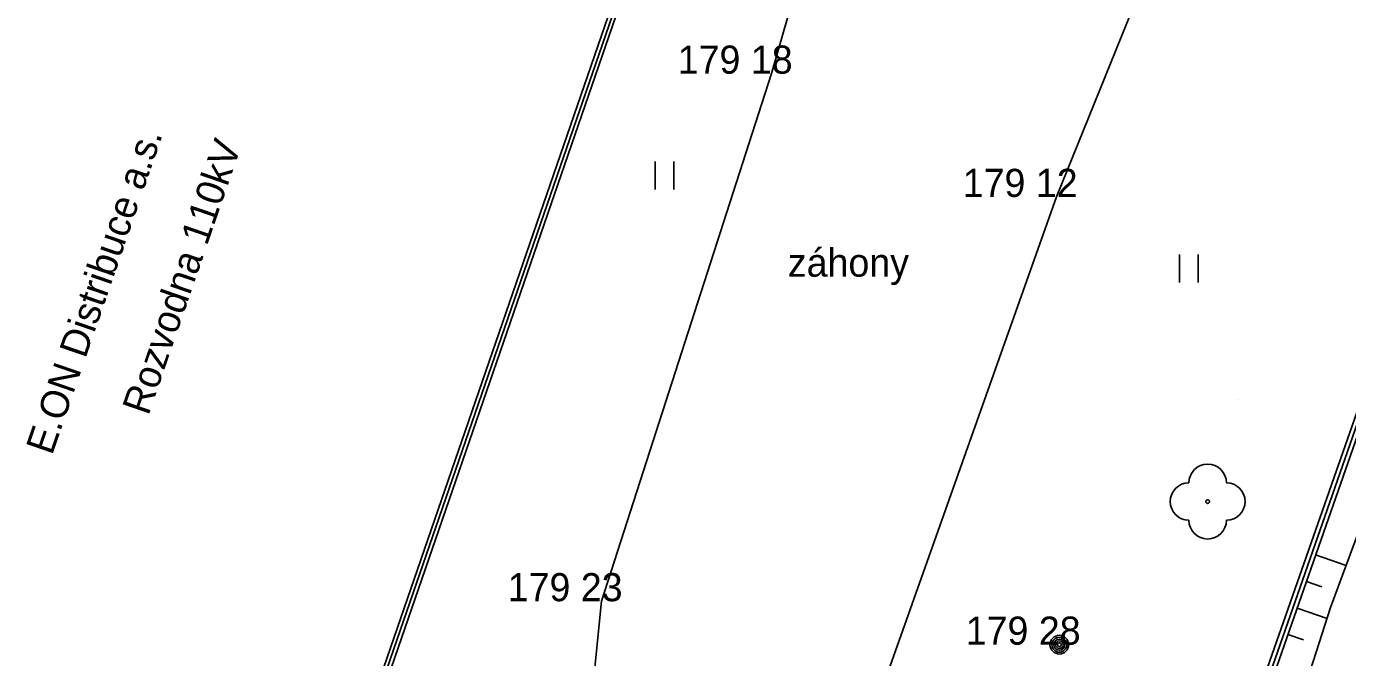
# Model space of a CAD drawing. Extents: x -537755 to -537431, y -1180722 to -1180510.
# Drawn here: x -537503.04 to -537467.76, y -1180590.89 to -1180574.05 of the extents above; entities that cross this region are included whole.
import ezdxf

# ---------------------------------------------------------------- set-up
doc = ezdxf.new("R2010")
doc.units = 0
for name, color, linetype in [('Vrstva 1', 7, 'Continuous'), ('Vrstva 14', 7, 'Continuous'), ('Vrstva 15', 7, 'Continuous'), ('Vrstva 22', 7, 'Continuous'), ('Vrstva 23', 7, 'Continuous'), ('Vrstva 25', 7, 'Continuous'), ('Vrstva 3', 7, 'Continuous'), ('Vrstva 36', 7, 'Continuous'), ('Vrstva 41', 7, 'Continuous'), ('Vrstva 7', 7, 'Continuous')]:
    doc.layers.add(name, color=color, linetype=linetype)

msp = doc.modelspace()

# ---------------------------------------------------------------- linework, layer by layer
at = {"layer": 'Vrstva 1'}
for p, q in [((-537483.15, -1180575.31), (-537483.15, -1180575.31)), ((-537475.54, -1180578.6), (-537475.54, -1180578.6)), ((-537470.67, -1180584.01), (-537470.67, -1180584.01)), ((-537471.5, -1180586.73), (-537471.5, -1180586.73)), ((-537487.69, -1180589.39), (-537487.69, -1180589.39)), ((-537468.22, -1180589.56), (-537468.22, -1180589.56)), ((-537475.46, -1180590.55), (-537475.46, -1180590.55))]:
    msp.add_line(p, q, dxfattribs=at)
at = {"layer": 'Vrstva 14'}
for p, q in [((-537464.22, -1180578.75), (-537468.22, -1180589.56)), ((-537468.22, -1180589.56), (-537470.51, -1180596.68))]:
    msp.add_line(p, q, dxfattribs=at)
at = {"layer": 'Vrstva 15'}
for p, q in [((-537467.805, -1180588.439), (-537468.617, -1180588.156)), ((-537468.448, -1180589.009), (-537468.864, -1180588.864)), ((-537468.313, -1180589.85), (-537469.111, -1180589.572)), ((-537468.942, -1180590.425), (-537469.358, -1180590.28))]:
    msp.add_line(p, q, dxfattribs=at)
at = {"layer": 'Vrstva 22'}
msp.add_circle((-537471.5, -1180586.73), 0.05, dxfattribs=at)
for centre, start, end in [((-537471.5, -1180586.23), 0, 180), ((-537472, -1180586.73), 90, 270), ((-537471, -1180586.73), 270, 90), ((-537471.5, -1180587.23), 180, 0)]:
    msp.add_arc(centre, 0.5, start, end, dxfattribs=at)
at = {"layer": 'Vrstva 23'}
for p, q in [((-537483.15, -1180575.31), (-537481.16, -1180568.35)), ((-537473, -1180572.34), (-537475.54, -1180578.6)), ((-537487.69, -1180589.39), (-537483.15, -1180575.31)), ((-537475.54, -1180578.6), (-537481.14, -1180594.38)), ((-537487.98, -1180592.38), (-537487.69, -1180589.39))]:
    msp.add_line(p, q, dxfattribs=at)
at = {"layer": 'Vrstva 25'}
for radius in [0.25, 0.2, 0.15, 0.1, 0.05]:
    msp.add_circle((-537475.46, -1180590.55), radius, dxfattribs=at)
at = {"layer": 'Vrstva 36'}
for p, q in [((-537486.251, -1180578.406), (-537486.251, -1180577.656)), ((-537485.751, -1180578.406), (-537485.751, -1180577.656)), ((-537472.255, -1180580.888), (-537472.255, -1180580.138)), ((-537471.755, -1180580.888), (-537471.755, -1180580.138))]:
    msp.add_line(p, q, dxfattribs=at)
at = {"layer": 'Vrstva 7'}
for p, q in [((-537477.608, -1180613.623), (-537461.55, -1180567.55)), ((-537461.41, -1180567.5), (-537475.176, -1180606.957)), ((-537461.663, -1180567.617), (-537473.031, -1180600.103)), ((-537485.37, -1180567.87), (-537494, -1180592.9)), ((-537485.241, -1180567.802), (-537493.873, -1180592.838)), ((-537486.442, -1180570.674), (-537494.127, -1180592.962))]:
    msp.add_line(p, q, dxfattribs=at)

# ---------------------------------------------------------------- texts
at = {"layer": 'Vrstva 3'}
for s, p in [('179 18 ', (-537485.65, -1180575.31)), ('179 12 ', (-537478.04, -1180578.6)), ('179 23 ', (-537490.19, -1180589.39)), ('179 28 ', (-537477.96, -1180590.55))]:
    msp.add_text(s, height=0.75, dxfattribs=at).set_placement(p)
at = {"layer": 'Vrstva 41'}
for s, p in [('E.ON Distribuce a.s.', (-537502.359, -1180585.517)), ('Rozvodna 110kV', (-537499.787, -1180584.457))]:
    msp.add_text(s, height=0.75, rotation=70.9765, dxfattribs=at).set_placement(p)
msp.add_text('záhony', height=0.75, dxfattribs=at).set_placement((-537482.709, -1180580.728))

doc.saveas('drawing.dxf')
